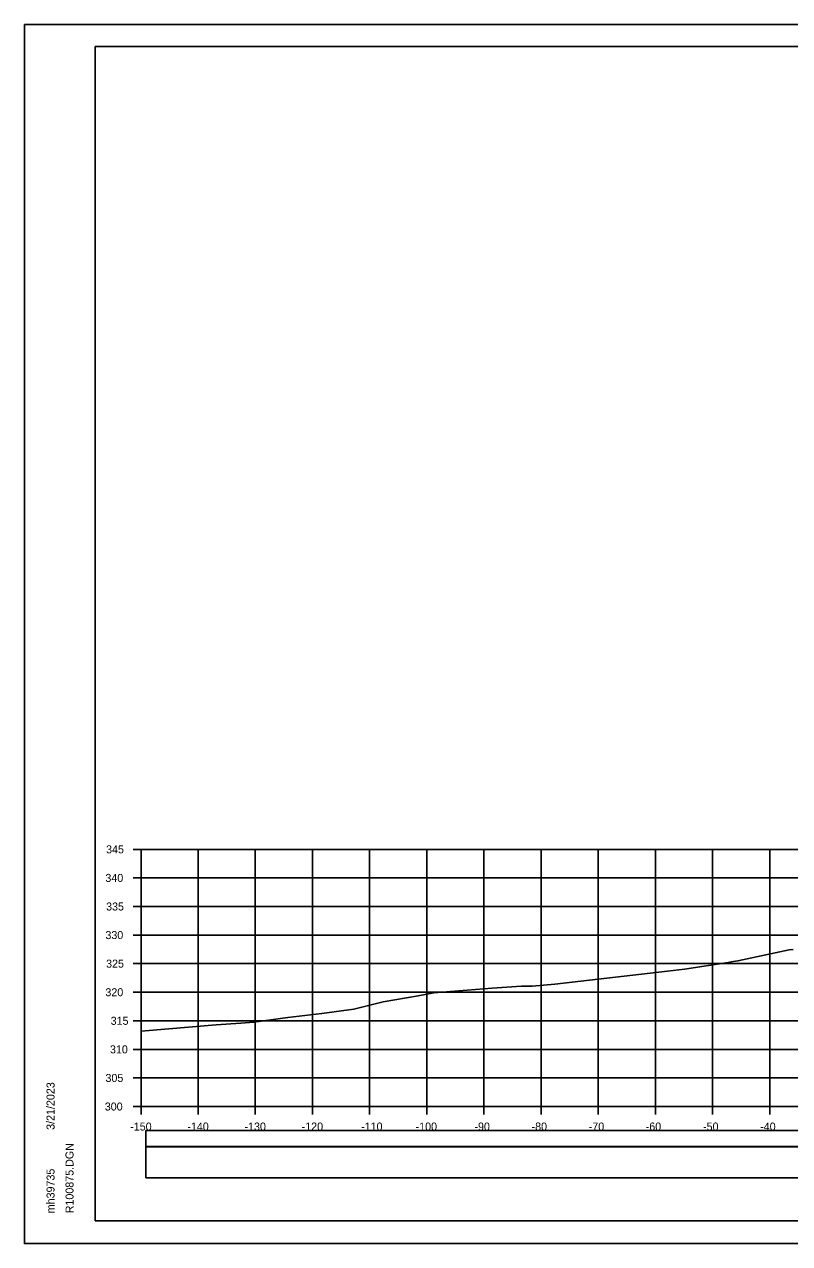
# Model space of a CAD drawing. Extents: x 1368122 to 1710785, y 373130 to 557566.
# Drawn here: x 1369185.2 to 1369319, y 375690.4 to 375903.7 of the extents above; entities that cross this region are included whole.
import ezdxf

# ---------------------------------------------------------------- set-up
doc = ezdxf.new("R2010")
doc.units = 0
for name, color, linetype in [('R_Axis', 7, 'Continuous'), ('R_Axis Annot', 7, 'Continuous'), ('R_Border', 7, 'Continuous'), ('R_Exist Surface', 7, 'Continuous'), ('R_Grid', 7, 'Continuous'), ('R_No Plot', 7, 'Continuous')]:
    doc.layers.add(name, color=color, linetype=linetype)

msp = doc.modelspace()

# ---------------------------------------------------------------- linework, layer by layer
for points in [[(1369206.41, 375707.36), (1369504.71, 375707.36), (1369504.71, 375710.17), (1369206.41, 375710.17)], [(1369206.41, 375701.89), (1369504.71, 375701.89), (1369504.71, 375707.3), (1369206.41, 375707.3)]]:
    msp.add_lwpolyline(points, close=True)
at = {"layer": 'R_Axis'}
for p, q in [((1369204.16, 375759.37), (1369205.56, 375759.37)), ((1369205.56, 375714.37), (1369205.56, 375759.37)), ((1369204.16, 375754.37), (1369205.56, 375754.37)), ((1369204.16, 375749.37), (1369205.56, 375749.37)), ((1369204.16, 375744.37), (1369205.56, 375744.37)), ((1369204.16, 375739.37), (1369205.56, 375739.37)), ((1369204.16, 375734.37), (1369205.56, 375734.37)), ((1369204.16, 375729.37), (1369205.56, 375729.37)), ((1369204.16, 375724.37), (1369205.56, 375724.37)), ((1369204.16, 375719.37), (1369205.56, 375719.37)), ((1369204.16, 375714.37), (1369205.56, 375714.37)), ((1369205.56, 375714.37), (1369505.56, 375714.37)), ((1369205.56, 375712.97), (1369205.56, 375714.37)), ((1369215.56, 375712.97), (1369215.56, 375714.37)), ((1369225.56, 375712.97), (1369225.56, 375714.37)), ((1369235.56, 375712.97), (1369235.56, 375714.37)), ((1369245.56, 375712.97), (1369245.56, 375714.37)), ((1369255.56, 375712.97), (1369255.56, 375714.37)), ((1369265.56, 375712.97), (1369265.56, 375714.37)), ((1369275.56, 375712.97), (1369275.56, 375714.37)), ((1369285.56, 375712.97), (1369285.56, 375714.37)), ((1369295.56, 375712.97), (1369295.56, 375714.37)), ((1369305.56, 375712.97), (1369305.56, 375714.37)), ((1369315.56, 375712.97), (1369315.56, 375714.37))]:
    msp.add_line(p, q, dxfattribs=at)
at = {"layer": 'R_Border'}
for p, q in [((1369197.56, 375899.83), (1369513.74, 375899.83)), ((1369197.56, 375694.37), (1369197.56, 375899.83)), ((1369197.56, 375694.37), (1369197.56, 375694.37)), ((1369513.74, 375694.37), (1369197.56, 375694.37))]:
    msp.add_line(p, q, dxfattribs=at)
at = {"layer": 'R_Exist Surface'}
msp.add_lwpolyline([(1369205.56, 375727.55), (1369218.7, 375728.65), (1369223.04, 375728.96), (1369225.31, 375729.14), (1369231.26, 375729.93), (1369237.18, 375730.63), (1369242.81, 375731.38), (1369247.93, 375732.7), (1369254.03, 375733.74), (1369256.78, 375734.29), (1369267, 375735.08), (1369272.13, 375735.42), (1369274.02, 375735.44), (1369277.97, 375735.77), (1369297.66, 375738.05), (1369300.65, 375738.42), (1369308.27, 375739.6), (1369309.17, 375739.74), (1369309.99, 375739.85), (1369318.95, 375741.78), (1369319.65, 375741.86)], dxfattribs=at)
at = {"layer": 'R_Grid'}
for p, q in [((1369205.56, 375759.37), (1369505.56, 375759.37)), ((1369205.56, 375714.37), (1369205.56, 375759.37)), ((1369215.56, 375714.37), (1369215.56, 375759.37)), ((1369225.56, 375714.37), (1369225.56, 375759.37)), ((1369235.56, 375714.37), (1369235.56, 375759.37)), ((1369245.56, 375714.37), (1369245.56, 375759.37)), ((1369255.56, 375714.37), (1369255.56, 375759.37)), ((1369265.56, 375714.37), (1369265.56, 375759.37)), ((1369275.56, 375714.37), (1369275.56, 375759.37)), ((1369285.56, 375714.37), (1369285.56, 375759.37)), ((1369295.56, 375714.37), (1369295.56, 375759.37)), ((1369305.56, 375714.37), (1369305.56, 375759.37)), ((1369315.56, 375714.37), (1369315.56, 375759.37)), ((1369205.56, 375754.37), (1369505.56, 375754.37)), ((1369205.56, 375749.37), (1369505.56, 375749.37)), ((1369205.56, 375744.37), (1369505.56, 375744.37)), ((1369205.56, 375739.37), (1369505.56, 375739.37)), ((1369205.56, 375734.37), (1369505.56, 375734.37)), ((1369205.56, 375729.37), (1369505.56, 375729.37)), ((1369205.56, 375724.37), (1369505.56, 375724.37)), ((1369205.56, 375719.37), (1369505.56, 375719.37)), ((1369205.56, 375714.37), (1369505.56, 375714.37))]:
    msp.add_line(p, q, dxfattribs=at)
at = {"layer": 'R_No Plot'}
for p, q in [((1369185.16, 375903.72), (1369518.49, 375903.72)), ((1369185.16, 375690.39), (1369518.49, 375690.39))]:
    msp.add_line(p, q, dxfattribs=at)
for points in [[(1369185.15, 375903.72), (1369518.49, 375903.72), (1369518.49, 375690.38), (1369185.15, 375690.38)], [(1369431.48, 375899.83), (1369451.1, 375899.83), (1369451.1, 375889.95), (1369467.21, 375889.95), (1369490.41, 375889.95), (1369490.53, 375861.79), (1369513.74, 375861.79), (1369513.74, 375694.37), (1369197.56, 375694.37), (1369197.56, 375899.83)]]:
    msp.add_lwpolyline(points, close=True, dxfattribs=at)

# ---------------------------------------------------------------- texts
at = {"layer": 'R_Axis Annot'}
for s, p in [('345', (1369199.45, 375758.67)), ('340', (1369199.33, 375753.67)), ('335', (1369199.45, 375748.67)), ('330', (1369199.33, 375743.67)), ('325', (1369199.45, 375738.67)), ('320', (1369199.33, 375733.67)), ('315', (1369200.25, 375728.67)), ('310', (1369200.13, 375723.67)), ('305', (1369199.34, 375718.67)), ('300', (1369199.22, 375713.67)), ('-150', (1369203.67, 375710.17)), ('-140', (1369213.67, 375710.17)), ('-130', (1369223.67, 375710.17)), ('-120', (1369233.67, 375710.17)), ('-110', (1369244.07, 375710.17)), ('-100', (1369253.61, 375710.17)), ('-90', (1369263.9, 375710.17)), ('-80', (1369273.9, 375710.17)), ('-70', (1369283.9, 375710.17)), ('-60', (1369293.87, 375710.17)), ('-50', (1369303.9, 375710.17)), ('-40', (1369313.9, 375710.17))]:
    msp.add_text(s, height=1.4, dxfattribs=at).set_placement(p)
at = {"layer": 'R_Border'}
for s, p in [('3/21/2023', (1369190.43, 375710.29)), ('R100875.DGN', (1369193.75, 375695.69)), ('mh39735', (1369190.43, 375695.69))]:
    msp.add_text(s, height=1.4, rotation=90, dxfattribs=at).set_placement(p)

doc.saveas('drawing.dxf')
